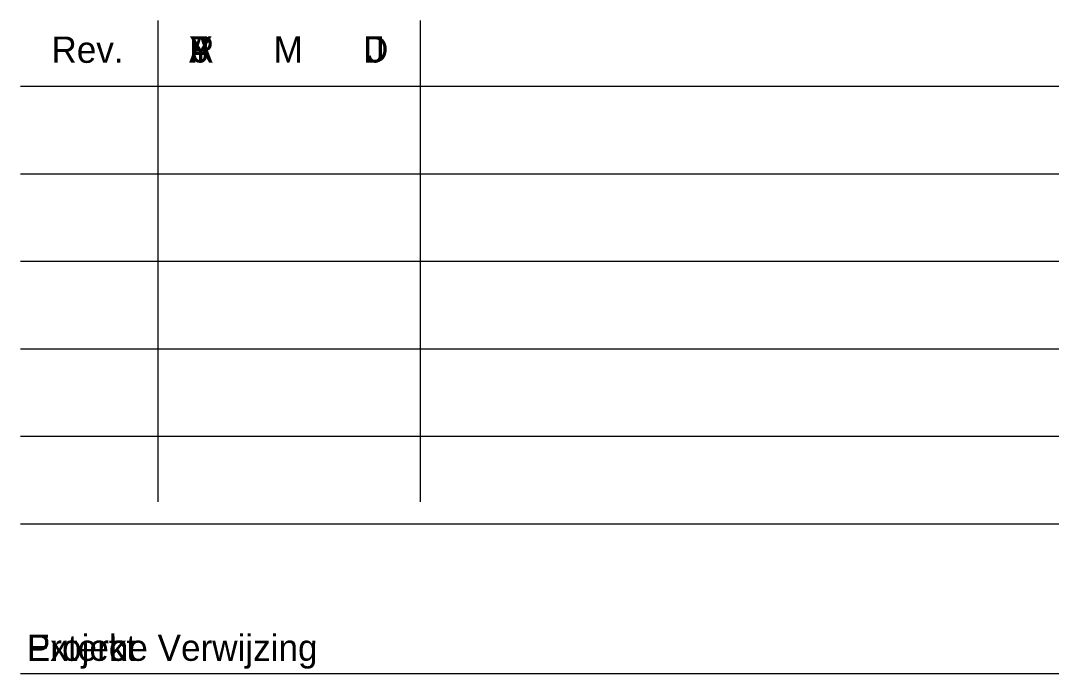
# Model space of a CAD drawing. Extents: x -932963 to -932666, y -737039 to -736000.
# Drawn here: x -932766.57 to -932737.11, y -736979.85 to -736961.2 of the extents above; entities that cross this region are included whole.
import ezdxf

# ---------------------------------------------------------------- set-up
doc = ezdxf.new("R2010")
doc.units = 0
for name, color, linetype in [('Border', 7, 'Continuous'), ('Border_TextCZ', 7, 'Continuous'), ('Border_TextFR', 7, 'Continuous'), ('Border_TextNL', 7, 'Continuous'), ('Border_TextUK', 7, 'Continuous')]:
    doc.layers.add(name, color=color, linetype=linetype)

# ---------------------------------------------------------------- blocks, each defined once
blk = doc.blocks.new('A2_v03_CZ')
at = {"layer": 'Border'}
blk.add_line((0.393583, 0.152058), (0.583583, 0.152058), dxfattribs=at)
for points in [[(0.401417, 0.155808), (0.401417, 0.128308)], [(0.416417, 0.155808), (0.416417, 0.128308)], [(0.393583, 0.152058), (0.584417, 0.152058)], [(0.393583, 0.147058), (0.584417, 0.147058)], [(0.393583, 0.142058), (0.584417, 0.142058)], [(0.393583, 0.137058), (0.584417, 0.137058)], [(0.393583, 0.132058), (0.584417, 0.132058)], [(0.393583, 0.127058), (0.584417, 0.127058)], [(0.393583, 0.118503), (0.584417, 0.118503)]]:
    blk.add_lwpolyline(points, dxfattribs=at)
at = {"layer": 'Border_TextCZ'}
for s, p in [('Rev.', (0.395345, 0.153396)), ('R', (0.403212, 0.15341)), ('M', (0.408039, 0.15341)), ('D', (0.413155, 0.15341)), ('Projekt', (0.393942, 0.119219))]:
    blk.add_text(s, height=0.0015, dxfattribs=at).set_placement(p)
at = {"layer": 'Border_TextFR'}
for s, p in [('Rev.', (0.395345, 0.153396)), ('A', (0.403212, 0.15341)), ('M', (0.408039, 0.15341)), ('J', (0.413388, 0.15341)), ('Projet', (0.393942, 0.119219))]:
    blk.add_text(s, height=0.0015, dxfattribs=at).set_placement(p)
at = {"layer": 'Border_TextNL'}
for s, p in [('Rev.', (0.395345, 0.153396)), ('J', (0.403388, 0.15341)), ('M', (0.408039, 0.15341)), ('D', (0.413155, 0.15341)), ('Externe Verwijzing', (0.393942, 0.119219))]:
    blk.add_text(s, height=0.0015, dxfattribs=at).set_placement(p)
at = {"layer": 'Border_TextUK'}
for s, p in [('Rev.', (0.395345, 0.153396)), ('Y', (0.403212, 0.15341)), ('M', (0.408039, 0.15341)), ('D', (0.413155, 0.15341)), ('Project', (0.393942, 0.119219))]:
    blk.add_text(s, height=0.0015, dxfattribs=at).set_placement(p)

msp = doc.modelspace()

# ---------------------------------------------------------------- block references
at = {"layer": 'Border', "xscale": 499.9999999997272, "yscale": 499.9999999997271, "rotation": -4.538738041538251e-11}
msp.add_blockref('A2_v03_CZ', (-932963.362, -737039.103), dxfattribs=at)

doc.saveas('drawing.dxf')
